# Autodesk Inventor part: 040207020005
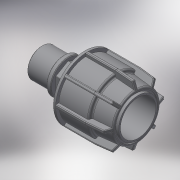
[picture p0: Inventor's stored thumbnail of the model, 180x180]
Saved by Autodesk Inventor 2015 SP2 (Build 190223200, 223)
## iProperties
Created: 2017-08
Part Number: 040207020005
Material: Generic
Description: PLASSON IRRIFIT ADAPTOR 20-1/2"M
Document SubType Name: Modeling
Designer: KIM
Density: 1 g/cm^3
Appearance: Default
Author: KIM
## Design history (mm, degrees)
derived "040207.ipt"
feature "Solid1::040207.ipt"
tag "TaggingFeature1"
body "Solid1"
other parameters: "d5" = 30.8, "d6" = 14.3, "d10" = 39, "d22" = 20.955, "d24" = 1.495, "d25" = 35.1, "d26" = 31.2, "d31" = 0.8, "d49" = 1.95, "d50" = 0, "d58" = 0.4, "d61" = 360 deg, "d78" = 5 deg, "d80" = 22, "d81" = 32.5, "d82" = 1.95, "d84" = 5 deg, "d85" = 70 deg, "d86" = 37.05, "d87" = 0.325, "d88" = 0, "d89" = 33.15, "d90" = 3.25, "d91" = 0, "d99" = 20.955, "d100" = 16, "d101" = 3.2, "d102" = 65, "d103" = 25.146, "d104" = 0.4191, "d108" = 0, "d109" = 0.20955, "d112" = 16.764, "d113" = 24.64, "E_" = 39, "H_" = 65, "l_nut" = 30.8, "l_" = 16, "R_" = 20.955
